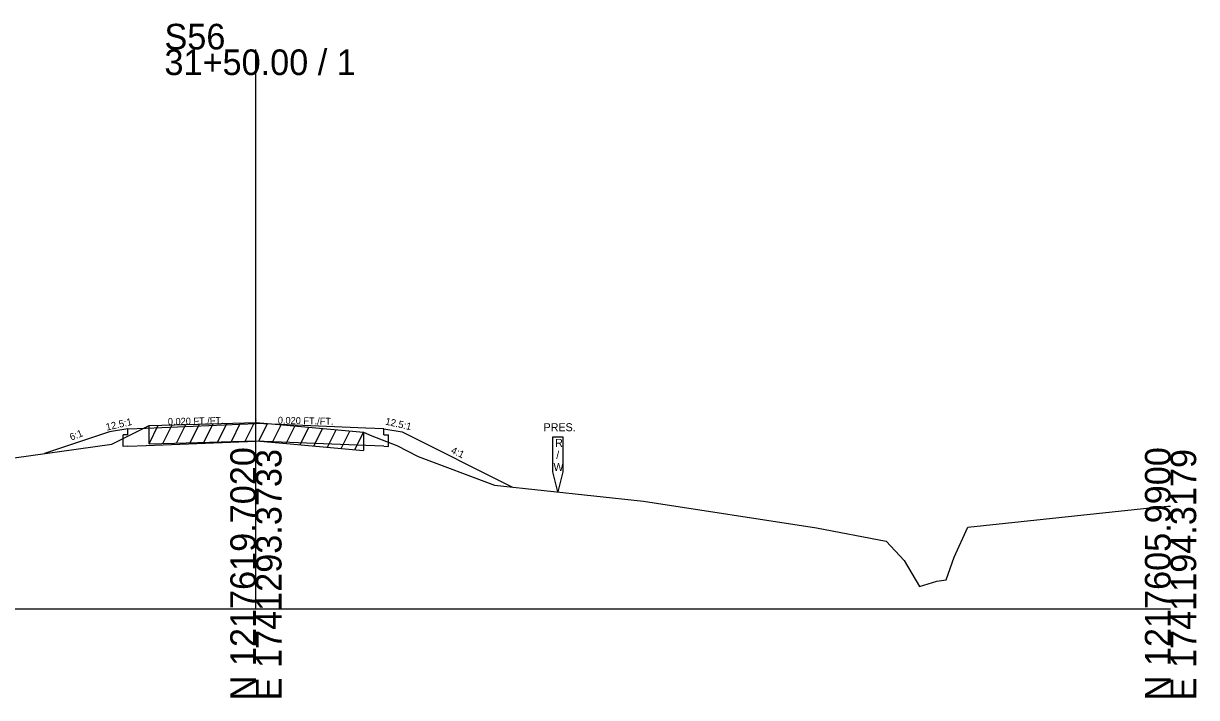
# Model space of a CAD drawing. Extents: x -26 to 1203, y -10 to 19541.
# Drawn here: x 74.6 to 202.8, y 6490.3 to 6564 of the extents above; entities that cross this region are included whole.
import ezdxf

# ---------------------------------------------------------------- set-up
doc = ezdxf.new("R2010")
doc.units = 0
for name, color, linetype in [('RD_GPK_XS_Cell', 7, 'Continuous'), ('RD_XS_Base', 7, 'Continuous'), ('RD_XS_EarthShd', 7, 'Continuous'), ('RD_XS_ExGround', 7, 'Continuous'), ('RD_XS_ExPaveRet', 7, 'Continuous'), ('RD_XS_ExRW', 7, 'Continuous'), ('RD_XS_Pave', 7, 'Continuous'), ('RD_XS_TX_Elev_EX', 7, 'Continuous'), ('RD_XS_TX_Slope', 7, 'Continuous')]:
    doc.layers.add(name, color=color, linetype=linetype)

msp = doc.modelspace()

# ---------------------------------------------------------------- linework, layer by layer
at = {"layer": 'RD_GPK_XS_Cell'}
for p, q in [((100, 6500), (100, 6561.18)), ((0, 6500), (100, 6500)), ((100, 6500), (200, 6500))]:
    msp.add_line(p, q, dxfattribs=at)
at = {"layer": 'RD_XS_Base'}
for p, q in [((86, 6519.05), (86, 6519.69)), ((114, 6519.05), (114, 6519.69)), ((86, 6519.05), (85.5, 6519.03)), ((85.5, 6517.76), (85.5, 6519.03)), ((88, 6517.86), (100, 6518.36)), ((112, 6517.86), (100, 6518.36)), ((114, 6519.05), (114.5, 6519.03)), ((114.5, 6517.76), (114.5, 6519.03)), ((86, 6517.78), (85.5, 6517.76)), ((86, 6517.78), (88, 6517.86)), ((114, 6517.78), (112, 6517.86)), ((114, 6517.78), (114.5, 6517.76))]:
    msp.add_line(p, q, dxfattribs=at)
at = {"layer": 'RD_XS_EarthShd'}
for p, q in [((84, 6519.35), (76.87, 6516.98)), ((86, 6519.69), (84, 6519.35)), ((114, 6519.69), (116, 6519.35)), ((116, 6519.35), (128.04, 6513.33))]:
    msp.add_line(p, q, dxfattribs=at)
at = {"layer": 'RD_XS_ExGround'}
msp.add_lwpolyline([(71.7, 6516.25), (84.26, 6518.01), (85.12, 6518.46), (88.32, 6520.06), (91.09, 6520.13), (100.04, 6520.38), (102.95, 6520.12), (111.77, 6519.32), (112.66, 6518.94), (115.42, 6517.86), (117.74, 6516.66), (126.09, 6513.54), (142.39, 6511.77), (161.28, 6508.86), (168.9, 6507.39), (170.87, 6505.28), (172.54, 6502.44), (174.45, 6503.04), (175.46, 6503.19), (176.35, 6505.64), (177.83, 6508.94), (197.74, 6511.05), (199.7, 6511.24), (200, 6511.23)], dxfattribs=at)
at = {"layer": 'RD_XS_ExPaveRet'}
for p, q in [((88.32, 6518.06), (89.33, 6520.09)), ((88.32, 6518.06), (88.32, 6520.06)), ((89.82, 6518.1), (90.83, 6520.13)), ((91.32, 6518.14), (92.33, 6520.17)), ((92.82, 6518.18), (93.83, 6520.21)), ((94.32, 6518.22), (95.33, 6520.25)), ((95.82, 6518.26), (96.83, 6520.29)), ((97.32, 6518.3), (98.33, 6520.33)), ((98.82, 6518.34), (99.83, 6520.37)), ((100.32, 6518.35), (101.27, 6520.27)), ((101.82, 6518.22), (102.77, 6520.14)), ((103.32, 6518.09), (104.27, 6520)), ((104.82, 6517.95), (105.77, 6519.86)), ((106.32, 6517.81), (107.27, 6519.73)), ((107.82, 6517.68), (108.77, 6519.59)), ((109.32, 6517.54), (110.27, 6519.45)), ((110.82, 6517.4), (111.77, 6519.32)), ((111.77, 6519.32), (111.77, 6517.32)), ((88.32, 6518.06), (91.09, 6518.13)), ((91.09, 6518.13), (100.04, 6518.38)), ((100.04, 6518.38), (102.95, 6518.12)), ((102.95, 6518.12), (111.77, 6517.32))]:
    msp.add_line(p, q, dxfattribs=at)
at = {"layer": 'RD_XS_ExRW'}
msp.add_lwpolyline([(132.45, 6518.81), (133.55, 6518.81), (133.55, 6514.98), (133, 6512.79), (132.45, 6514.98)], close=True, dxfattribs=at)
at = {"layer": 'RD_XS_Pave'}
for p, q in [((86, 6519.69), (88, 6519.77)), ((88, 6519.77), (100, 6520.27)), ((112, 6519.77), (100, 6520.27)), ((114, 6519.69), (112, 6519.77))]:
    msp.add_line(p, q, dxfattribs=at)

# ---------------------------------------------------------------- texts
at = {"layer": 'RD_GPK_XS_Cell'}
for s, p in [('S56', (90, 6561.18)), ('31+50.00 / 1', (90, 6558.38))]:
    msp.add_text(s, height=2.8, dxfattribs=at).set_placement(p)
for s, p in [('N 1217619.7020', (100, 6490)), ('E 1741293.3733', (102.8, 6490)), ('N 1217605.9900', (200, 6490)), ('E 1741194.3179', (202.8, 6490))]:
    msp.add_text(s, height=2.8, rotation=90, dxfattribs=at).set_placement(p)
at = {"layer": 'RD_XS_ExRW'}
for s, p in [('PRES.', (131.45, 6519.43)), ('R', (132.71, 6517.72)), ('/', (132.83, 6516.4)), ('W', (132.53, 6515.09))]:
    msp.add_text(s, height=0.875, dxfattribs=at).set_placement(p)
at = {"layer": 'RD_XS_TX_Elev_EX'}
msp.add_text('849.19', height=0.1, rotation=90, dxfattribs=at).set_placement((100.1, 6520.38))
at = {"layer": 'RD_XS_TX_Slope'}
for s, height, rotation, p in [('12.5:1', 0.778, 12.7511, (83.69, 6519.49)), ('0.020 FT./FT.', 0.7518, 1.1916, (90.38, 6520.11)), ('0.020 FT./FT.', 0.7518, 358.8084, (102.39, 6520.26)), ('12.5:1', 0.778, 347.2489, (114.09, 6520.17)), ('6:1', 0.778, 21.2036, (79.81, 6518.39)), ('4:1', 0.778, 335.081, (121.25, 6517.07))]:
    msp.add_text(s, height=height, rotation=rotation, dxfattribs=at).set_placement(p)

doc.saveas('drawing.dxf')
